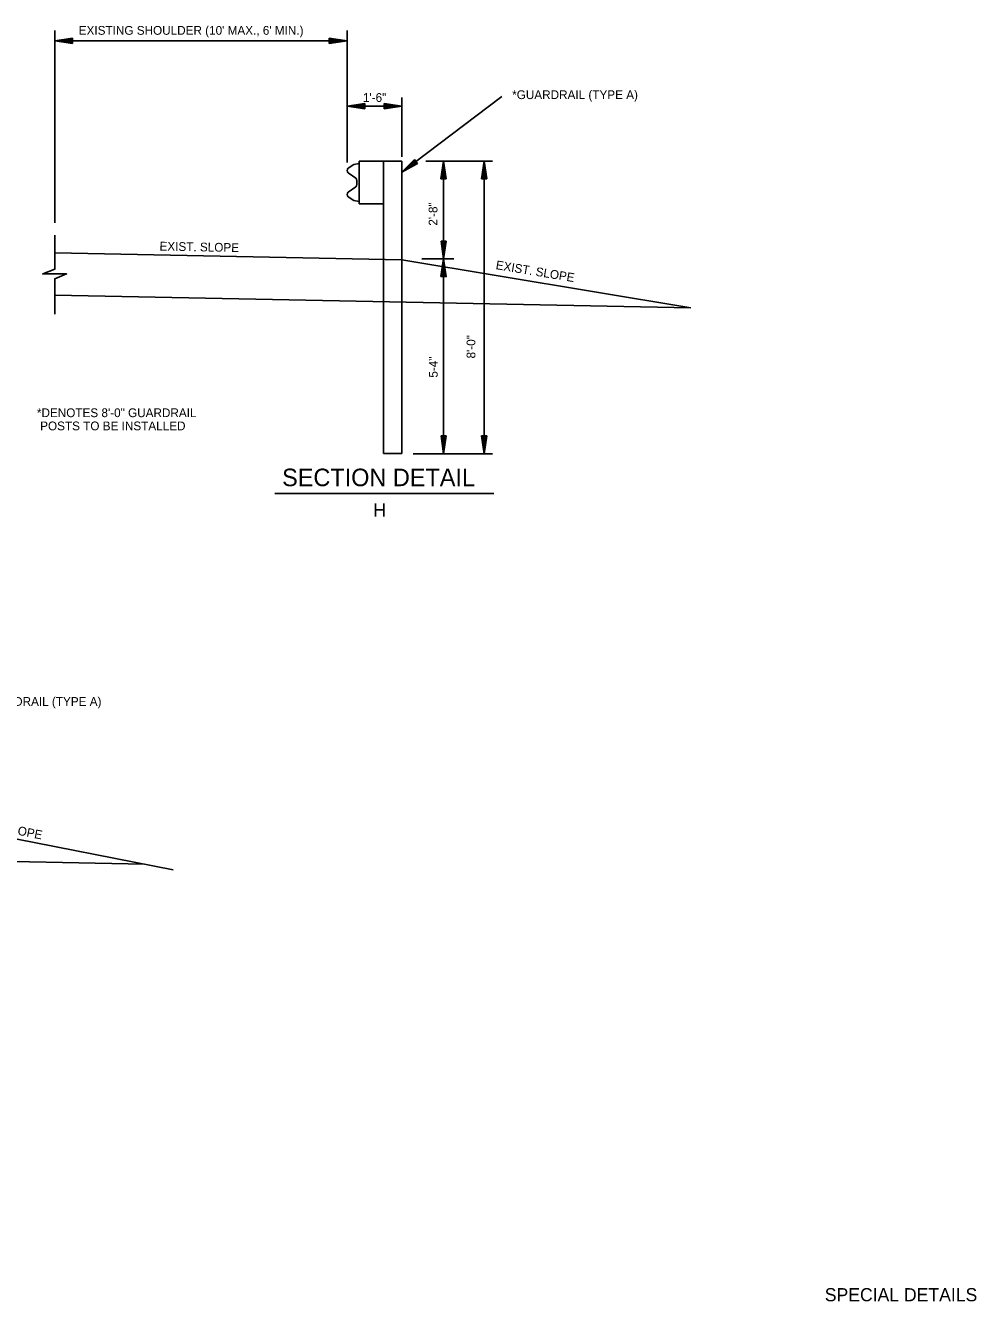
# Model space of a CAD drawing. Extents: x 1374136 to 1374281, y 380549 to 380948.
# Drawn here: x 1374215.8 to 1374280.9, y 380548.8 to 380636 of the extents above; entities that cross this region are included whole.
import ezdxf

# ---------------------------------------------------------------- set-up
doc = ezdxf.new("R2010")
doc.units = 0
for name, color, linetype in [('C-ANNO-TEXT', 7, 'Continuous'), ('Default', 7, 'Continuous'), ('G-ANNO-TEXT', 7, 'Continuous'), ('R_Draft', 7, 'Continuous')]:
    doc.layers.add(name, color=color, linetype=linetype)

msp = doc.modelspace()

# ---------------------------------------------------------------- linework, layer by layer
at = {"layer": 'C-ANNO-TEXT'}
msp.add_lwpolyline([(1374217.832, 380621.692), (1374217.832, 380619.362), (1374217.021, 380619.038), (1374218.643, 380619.038), (1374217.832, 380618.714), (1374217.832, 380616.29)], dxfattribs=at)
at = {"layer": 'Default'}
for p, q in [((1374217.832, 380622.537), (1374217.832, 380635.701)), ((1374219.049, 380635.159), (1374217.832, 380634.976)), ((1374217.832, 380634.976), (1374237.832, 380634.976)), ((1374219.05, 380634.793), (1374217.832, 380634.976)), ((1374219.049, 380635.128), (1374218.036, 380634.976)), ((1374219.05, 380634.824), (1374218.036, 380634.976)), ((1374219.049, 380635.096), (1374218.245, 380634.976)), ((1374219.05, 380634.856), (1374218.245, 380634.976)), ((1374219.049, 380635.067), (1374218.449, 380634.977)), ((1374219.05, 380634.885), (1374218.449, 380634.977)), ((1374219.049, 380635.036), (1374218.653, 380634.977)), ((1374219.05, 380634.916), (1374218.653, 380634.977)), ((1374219.05, 380635.004), (1374218.858, 380634.977)), ((1374219.05, 380634.948), (1374218.858, 380634.977)), ((1374219.05, 380634.793), (1374219.049, 380635.159)), ((1374236.615, 380635.159), (1374237.832, 380634.976)), ((1374236.615, 380634.793), (1374236.615, 380635.159)), ((1374236.615, 380635.128), (1374237.628, 380634.976)), ((1374236.615, 380635.096), (1374237.419, 380634.976)), ((1374236.615, 380635.067), (1374237.215, 380634.977)), ((1374236.615, 380635.036), (1374237.011, 380634.977)), ((1374236.615, 380635.004), (1374236.807, 380634.977)), ((1374236.615, 380634.916), (1374237.011, 380634.977)), ((1374236.615, 380634.885), (1374237.215, 380634.977)), ((1374236.615, 380634.948), (1374236.807, 380634.977)), ((1374236.615, 380634.793), (1374237.832, 380634.976)), ((1374236.615, 380634.856), (1374237.419, 380634.976)), ((1374236.615, 380634.824), (1374237.628, 380634.976)), ((1374237.832, 380626.671), (1374237.832, 380635.701)), ((1374239.049, 380630.699), (1374237.832, 380630.516)), ((1374237.832, 380630.516), (1374241.582, 380630.516)), ((1374239.05, 380630.332), (1374237.832, 380630.516)), ((1374239.049, 380630.667), (1374238.036, 380630.516)), ((1374239.05, 380630.364), (1374238.036, 380630.516)), ((1374239.049, 380630.636), (1374238.245, 380630.516)), ((1374239.05, 380630.395), (1374238.245, 380630.516)), ((1374239.049, 380630.607), (1374238.449, 380630.516)), ((1374239.05, 380630.424), (1374238.449, 380630.516)), ((1374239.049, 380630.575), (1374238.653, 380630.516)), ((1374239.05, 380630.456), (1374238.653, 380630.516)), ((1374239.05, 380630.544), (1374238.858, 380630.517)), ((1374239.05, 380630.488), (1374238.858, 380630.517)), ((1374239.05, 380630.332), (1374239.049, 380630.699)), ((1374240.365, 380630.699), (1374241.582, 380630.516)), ((1374240.365, 380630.332), (1374240.365, 380630.699)), ((1374240.365, 380630.667), (1374241.378, 380630.516)), ((1374240.365, 380630.636), (1374241.169, 380630.516)), ((1374240.365, 380630.607), (1374240.965, 380630.516)), ((1374240.365, 380630.575), (1374240.761, 380630.516)), ((1374240.365, 380630.544), (1374240.557, 380630.517)), ((1374240.365, 380630.488), (1374240.557, 380630.517)), ((1374240.365, 380630.332), (1374241.582, 380630.516)), ((1374240.365, 380630.456), (1374240.761, 380630.516)), ((1374240.365, 380630.395), (1374241.169, 380630.516)), ((1374240.365, 380630.364), (1374241.378, 380630.516)), ((1374240.365, 380630.424), (1374240.965, 380630.516)), ((1374241.582, 380625.996), (1374248.427, 380631.169)), ((1374241.582, 380627.057), (1374241.582, 380631.108)), ((1374238.294, 380626.535), (1374237.918, 380626.283)), ((1374238.657, 380626.605), (1374238.294, 380626.535)), ((1374238.657, 380626.763), (1374241.582, 380626.763)), ((1374238.657, 380626.763), (1374238.657, 380623.838)), ((1374240.332, 380626.763), (1374240.332, 380606.763)), ((1374242.444, 380626.874), (1374241.582, 380625.996)), ((1374241.582, 380626.763), (1374241.582, 380606.763)), ((1374242.662, 380626.586), (1374241.582, 380625.996)), ((1374242.465, 380626.851), (1374241.744, 380626.116)), ((1374242.647, 380626.608), (1374241.744, 380626.116)), ((1374242.485, 380626.823), (1374241.916, 380626.248)), ((1374242.624, 380626.634), (1374241.916, 380626.248)), ((1374242.498, 380626.798), (1374242.076, 380626.369)), ((1374242.606, 380626.659), (1374242.076, 380626.369)), ((1374242.518, 380626.778), (1374242.237, 380626.492)), ((1374242.585, 380626.685), (1374242.237, 380626.492)), ((1374242.536, 380626.752), (1374242.401, 380626.615)), ((1374242.572, 380626.712), (1374242.401, 380626.615)), ((1374242.662, 380626.586), (1374242.444, 380626.874)), ((1374247.792, 380626.763), (1374243.221, 380626.763)), ((1374244.256, 380625.546), (1374244.439, 380626.763)), ((1374244.283, 380625.545), (1374244.437, 380626.562)), ((1374244.317, 380625.548), (1374244.438, 380626.344)), ((1374244.348, 380625.547), (1374244.437, 380626.144)), ((1374244.587, 380625.543), (1374244.437, 380626.562)), ((1374244.524, 380625.548), (1374244.437, 380626.144)), ((1374244.552, 380625.544), (1374244.438, 380626.344)), ((1374244.617, 380625.545), (1374244.439, 380626.763)), ((1374244.439, 380620.073), (1374244.439, 380626.763)), ((1374247.024, 380625.546), (1374247.207, 380626.763)), ((1374247.051, 380625.545), (1374247.205, 380626.562)), ((1374247.086, 380625.548), (1374247.206, 380626.344)), ((1374247.116, 380625.547), (1374247.206, 380626.144)), ((1374247.355, 380625.543), (1374247.205, 380626.562)), ((1374247.32, 380625.544), (1374247.206, 380626.344)), ((1374247.292, 380625.548), (1374247.206, 380626.144)), ((1374247.385, 380625.545), (1374247.207, 380626.763)), ((1374247.207, 380606.748), (1374247.207, 380626.763)), ((1374237.915, 380625.962), (1374238.427, 380625.604)), ((1374238.509, 380625.444), (1374238.509, 380625.301)), ((1374238.509, 380625.301), (1374238.509, 380625.157)), ((1374244.256, 380625.546), (1374244.617, 380625.545)), ((1374244.381, 380625.547), (1374244.438, 380625.942)), ((1374244.411, 380625.541), (1374244.438, 380625.736)), ((1374244.496, 380625.545), (1374244.438, 380625.942)), ((1374244.465, 380625.546), (1374244.438, 380625.736)), ((1374247.024, 380625.546), (1374247.385, 380625.545)), ((1374247.15, 380625.547), (1374247.206, 380625.942)), ((1374247.179, 380625.541), (1374247.206, 380625.736)), ((1374247.265, 380625.545), (1374247.206, 380625.942)), ((1374247.233, 380625.546), (1374247.206, 380625.736)), ((1374238.427, 380624.998), (1374237.915, 380624.639)), ((1374237.918, 380624.318), (1374238.294, 380624.066)), ((1374238.294, 380624.066), (1374238.657, 380623.996)), ((1374238.657, 380623.838), (1374240.332, 380623.838)), ((1374244.263, 380621.291), (1374244.439, 380620.073)), ((1374244.263, 380621.291), (1374244.624, 380621.29)), ((1374244.29, 380621.292), (1374244.438, 380620.274)), ((1374244.324, 380621.289), (1374244.441, 380620.492)), ((1374244.355, 380621.29), (1374244.441, 380620.692)), ((1374244.388, 380621.289), (1374244.443, 380620.894)), ((1374244.418, 380621.295), (1374244.443, 380621.1)), ((1374244.594, 380621.292), (1374244.438, 380620.274)), ((1374244.624, 380621.29), (1374244.439, 380620.073)), ((1374244.558, 380621.292), (1374244.441, 380620.492)), ((1374244.531, 380621.287), (1374244.441, 380620.692)), ((1374244.503, 380621.291), (1374244.443, 380620.894)), ((1374244.471, 380621.29), (1374244.443, 380621.1)), ((1374217.832, 380620.488), (1374241.582, 380620.013)), ((1374241.582, 380620.013), (1374261.355, 380616.718)), ((1374245.13, 380620.073), (1374242.953, 380620.073)), ((1374244.256, 380618.856), (1374244.439, 380620.073)), ((1374244.617, 380618.855), (1374244.439, 380620.073)), ((1374244.439, 380620.073), (1374244.439, 380606.748)), ((1374244.283, 380618.855), (1374244.437, 380619.871)), ((1374244.317, 380618.858), (1374244.438, 380619.654)), ((1374244.348, 380618.857), (1374244.437, 380619.454)), ((1374244.381, 380618.857), (1374244.438, 380619.252)), ((1374244.587, 380618.853), (1374244.437, 380619.871)), ((1374244.524, 380618.858), (1374244.437, 380619.454)), ((1374244.552, 380618.854), (1374244.438, 380619.654)), ((1374244.496, 380618.855), (1374244.438, 380619.252)), ((1374244.256, 380618.856), (1374244.617, 380618.855)), ((1374244.411, 380618.851), (1374244.438, 380619.046)), ((1374244.465, 380618.856), (1374244.438, 380619.046)), ((1374217.832, 380617.588), (1374261.355, 380616.718)), ((1374244.263, 380607.966), (1374244.439, 380606.748)), ((1374244.263, 380607.966), (1374244.624, 380607.965)), ((1374244.29, 380607.967), (1374244.438, 380606.949)), ((1374244.324, 380607.964), (1374244.441, 380607.167)), ((1374244.355, 380607.965), (1374244.441, 380607.367)), ((1374244.388, 380607.964), (1374244.443, 380607.569)), ((1374244.418, 380607.97), (1374244.443, 380607.775)), ((1374244.594, 380607.967), (1374244.438, 380606.949)), ((1374244.624, 380607.965), (1374244.439, 380606.748)), ((1374244.558, 380607.967), (1374244.441, 380607.167)), ((1374244.531, 380607.962), (1374244.441, 380607.367)), ((1374244.503, 380607.966), (1374244.443, 380607.569)), ((1374244.471, 380607.965), (1374244.443, 380607.775)), ((1374247.031, 380607.966), (1374247.207, 380606.748)), ((1374247.031, 380607.966), (1374247.392, 380607.965)), ((1374247.058, 380607.967), (1374247.206, 380606.949)), ((1374247.092, 380607.964), (1374247.209, 380607.167)), ((1374247.123, 380607.965), (1374247.209, 380607.367)), ((1374247.156, 380607.964), (1374247.211, 380607.569)), ((1374247.186, 380607.97), (1374247.211, 380607.775)), ((1374247.362, 380607.967), (1374247.206, 380606.949)), ((1374247.392, 380607.965), (1374247.207, 380606.748)), ((1374247.327, 380607.967), (1374247.209, 380607.167)), ((1374247.299, 380607.962), (1374247.209, 380607.367)), ((1374247.271, 380607.966), (1374247.211, 380607.569)), ((1374247.24, 380607.965), (1374247.211, 380607.775)), ((1374247.792, 380606.748), (1374242.356, 380606.748)), ((1374232.89, 380604.025), (1374247.874, 380604.025)), ((1374202.694, 380582.848), (1374225.934, 380578.287)), ((1374180.769, 380579.536), (1374223.971, 380578.672))]:
    msp.add_line(p, q, dxfattribs=at)
for centre, start, end in [((1374238.027, 380626.121), 124.15804, 234.74711), ((1374238.314, 380625.444), 360, 54.74711), ((1374238.027, 380624.48), 125.25289, 235.84196), ((1374238.314, 380625.157), 305.25289, 0)]:
    msp.add_arc(centre, 0.195, start, end, dxfattribs=at)
at = {"layer": 'R_Draft'}
msp.add_line((1374240.332, 380606.763), (1374241.582, 380606.763), dxfattribs=at)

# ---------------------------------------------------------------- texts
at = {"layer": 'Default'}
for s, height, p in [("EXISTING SHOULDER (10' MAX., 6' MIN.)", 0.6, (1374219.479, 380635.401)), ('1\'-6"', 0.6, (1374238.919, 380630.808)), ('*GUARDRAIL (TYPE A)', 0.6, (1374249.127, 380631.002)), ('*DENOTES 8\'-0" GUARDRAIL', 0.6, (1374216.617, 380609.247)), (' POSTS TO BE INSTALLED', 0.6, (1374216.617, 380608.347)), ('SECTION DETAIL', 1.2, (1374233.39, 380604.525)), ('H', 0.9, (1374239.627, 380602.442)), ('GUARDRAIL (TYPE A)', 0.6, (1374212.739, 380589.5))]:
    msp.add_text(s, height=height, dxfattribs=at).set_placement(p)
for s, rotation, p in [('2\'-8"', 90, (1374244.016, 380622.343)), ('EXIST. SLOPE', 358.85424, (1374224.999, 380620.645)), ('EXIST. SLOPE', 350.53768, (1374247.974, 380619.377)), ('8\'-0"', 90, (1374246.611, 380613.261)), ('5-4"', 90, (1374244.033, 380611.947)), ('EXIST. SLOPE', 348.8964, (1374211.585, 380581.409))]:
    msp.add_text(s, height=0.6, rotation=rotation, dxfattribs=at).set_placement(p)
at = {"layer": 'G-ANNO-TEXT'}
msp.add_text('SPECIAL DETAILS', height=0.9, dxfattribs=at).set_placement((1374270.512, 380548.773))

doc.saveas('drawing.dxf')
